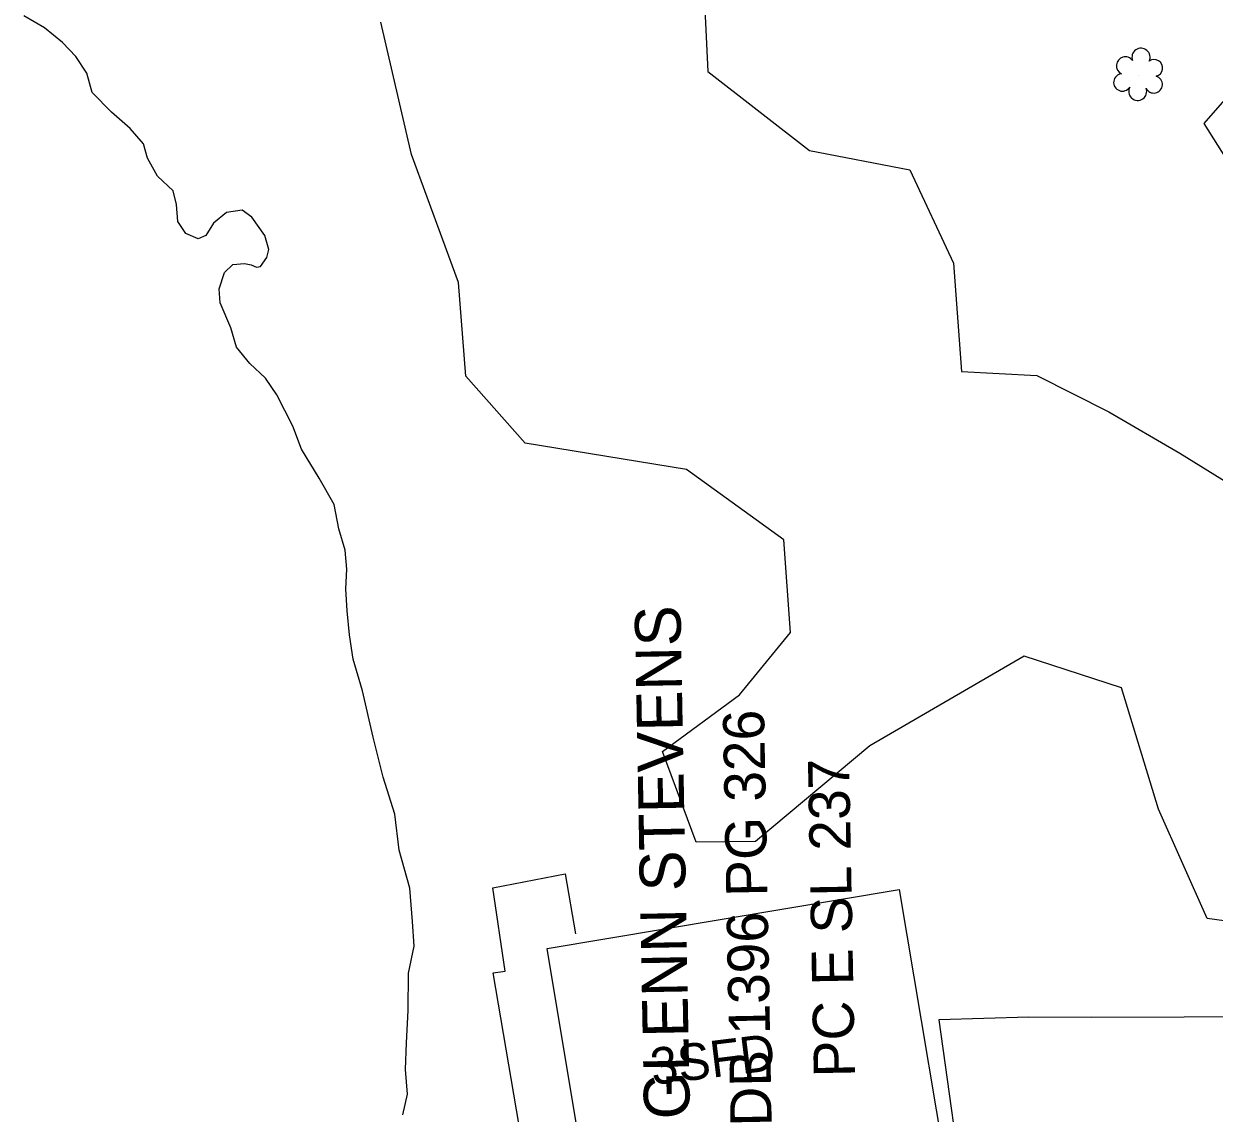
# Model space of a CAD drawing. Extents: x 3040896 to 3051146, y 687568 to 732976.
# Drawn here: x 3049308.6 to 3049438.5, y 692406.7 to 692525.6 of the extents above; entities that cross this region are included whole.
import ezdxf

# ---------------------------------------------------------------- set-up
doc = ezdxf.new("R2010")
doc.units = 0
for name, color, linetype in [('Exist Building', 7, 'Continuous'), ('Exist Building Text', 7, 'Continuous'), ('Exist Hydro Stream or Body of Water', 7, 'Continuous'), ('Exist Other Culture Area Outline', 7, 'Continuous'), ('Exist Property Deed Book Text', 7, 'Continuous'), ('Exist Property Owner Text', 7, 'Continuous'), ('Exist Roads Soil', 7, 'Continuous'), ('Exist Vegetation Shrub CELL', 7, 'Continuous'), ('Exist Vegetation Woods Line', 7, 'Continuous')]:
    doc.layers.add(name, color=color, linetype=linetype)

msp = doc.modelspace()

# ---------------------------------------------------------------- linework, layer by layer
at = {"layer": 'Exist Building'}
msp.add_lwpolyline([(3049365.68, 692424.68), (3049404.13, 692431.12), (3049410.56, 692392.79), (3049392.73, 692389.8), (3049394.07, 692381.84), (3049375.54, 692378.73), (3049371.58, 692402.32), (3049369.48, 692401.96)], close=True, dxfattribs=at)
at = {"layer": 'Exist Hydro Stream or Body of Water'}
msp.add_lwpolyline([(3049349.93, 692406.55), (3049350.44, 692408.78), (3049350.24, 692411.48), (3049350.33, 692414.41), (3049350.51, 692417.93), (3049350.56, 692422.01), (3049351.18, 692424.93), (3049350.99, 692427.63), (3049350.71, 692431.28), (3049349.55, 692435.42), (3049349.06, 692439.37), (3049347.78, 692443.39), (3049346.69, 692447.76), (3049345.52, 692452.83), (3049344.52, 692456.28), (3049344.13, 692458.93), (3049343.86, 692461.57), (3049343.72, 692463.96), (3049343.83, 692466.11), (3049343.66, 692468.16), (3049342.97, 692470.5), (3049342.45, 692473.16), (3049340.8, 692476.05), (3049338.88, 692479.2), (3049337.92, 692481.7), (3049336.19, 692485.15), (3049334.96, 692486.95), (3049333.23, 692488.57), (3049331.77, 692490.33), (3049331.17, 692492.43), (3049330, 692495.16), (3049329.89, 692496.72), (3049330.46, 692498.47), (3049331.37, 692499.35), (3049332.66, 692499.48), (3049333.37, 692499.32), (3049333.98, 692499.06), (3049334.4, 692499.14), (3049335.08, 692500.13), (3049335.31, 692500.99), (3049334.88, 692502.53), (3049333.46, 692504.52), (3049332.39, 692505.28), (3049330.69, 692505.04), (3049329.26, 692503.87), (3049328.43, 692502.52), (3049327.58, 692502.17), (3049326.25, 692502.74), (3049325.39, 692504.04), (3049325.23, 692505.91), (3049324.88, 692507.41), (3049323.17, 692509), (3049322.07, 692510.97), (3049321.62, 692512.54), (3049320.18, 692514.2), (3049318.14, 692516), (3049316.02, 692518.13), (3049315.43, 692520.26), (3049314.23, 692522.06), (3049312.79, 692523.58), (3049310.81, 692525.18), (3049308.56, 692526.52)], dxfattribs=at)
at = {"layer": 'Exist Other Culture Area Outline'}
msp.add_lwpolyline([(3049374.02, 692380.25), (3049367.15, 692378.88), (3049359.81, 692422.03), (3049361.1, 692422.22), (3049359.78, 692431.31), (3049367.66, 692432.86), (3049368.78, 692426.29)], dxfattribs=at)
at = {"layer": 'Exist Roads Soil'}
msp.add_lwpolyline([(3049445.27, 692417.27), (3049435.26, 692417.2), (3049425.12, 692417.17), (3049418.27, 692417.21), (3049408.45, 692416.92), (3049411.42, 692395.81)], dxfattribs=at)
at = {"layer": 'Exist Vegetation Shrub CELL'}
msp.add_line((3049430.3, 692519.94), (3049430.3, 692519.94), dxfattribs=at)
for centre, radius, start, end in [((3049430.53, 692521.98), 0.99, 334.8391, 200.4717), ((3049428.81, 692521.07), 0.968, 35.8908, 245.4216), ((3049431.97, 692520.81), 0.929, 284.4567, 126.0861), ((3049428.5, 692519.24), 0.955, 95.1099, 327.9534), ((3049431.93, 692519.01), 0.937, 204.9913, 73.4601), ((3049430.17, 692518.26), 0.984, 151.2797, 21.387)]:
    msp.add_arc(centre, radius, start, end, dxfattribs=at)
at = {"layer": 'Exist Vegetation Woods Line'}
for points in [[(3049441.93, 692559.06), (3049427.53, 692553.54), (3049419.6, 692553.46), (3049413.1, 692556.45), (3049409.51, 692550.23), (3049402.18, 692542.02), (3049391.1, 692534.13), (3049382.72, 692531.05), (3049383.23, 692520.42), (3049394.34, 692511.81), (3049405.3, 692509.69), (3049410.05, 692499.52), (3049410.95, 692487.67), (3049419.16, 692487.23), (3049427.03, 692483.26), (3049434.77, 692478.76), (3049443.64, 692473.26)], [(3049450.98, 692426.13), (3049437.74, 692427.95), (3049432.43, 692439.9), (3049428.4, 692453.16), (3049417.76, 692456.6), (3049400.92, 692446.81), (3049388.43, 692436.38), (3049381.96, 692436.29), (3049378.29, 692446.21), (3049386.71, 692452.38), (3049392.26, 692459.19), (3049391.54, 692469.31), (3049380.92, 692476.98), (3049363.31, 692479.87), (3049356.81, 692487.16), (3049356, 692497.38), (3049350.89, 692511.37), (3049347.55, 692525.8)], [(3049440.42, 692510.02), (3049437.42, 692514.76), (3049442.45, 692520.49)]]:
    msp.add_lwpolyline(points, dxfattribs=at)

# ---------------------------------------------------------------- texts
at = {"layer": 'Exist Building Text'}
msp.add_text('3SFD', height=4, rotation=7.0379, dxfattribs=at).set_placement((3049377.23, 692409.78))
at = {"layer": 'Exist Property Deed Book Text'}
for s, p in [('DB 1396 PG 326', (3049390.22, 692405.3)), ('PC E SL 237', (3049399.31, 692410.67))]:
    msp.add_text(s, height=4.5, rotation=91.0656, dxfattribs=at).set_placement(p)
at = {"layer": 'Exist Property Owner Text'}
msp.add_text('W. GLENN STEVENS', height=5, rotation=91.0656, dxfattribs=at).set_placement((3049381.48, 692396.06))

doc.saveas('drawing.dxf')
